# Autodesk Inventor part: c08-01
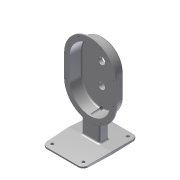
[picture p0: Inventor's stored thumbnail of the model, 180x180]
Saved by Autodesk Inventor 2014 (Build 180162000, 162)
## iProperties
Created: 2010-12
Part Number: c08-01
Document SubType Name: Modeling
Designer: Thom Tremblay
Density: 7.25 g/cm^3
Material: Iron, Cast
Mass: 1233.53 g
Surface Area: 883.619 cm^2
Volume: 170.142 cm^3
Appearance: Steel
Author: Thom Tremblay
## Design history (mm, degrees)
sketch "Sketch1"
  geometry: L1 (-50, -50)-(-50, 0); L2 (50, 0)-(50, -50); L3 (-60, 0)-(-60, -50); L4 (60, -50)-(60, 0); A1 r 50 centre (0, 0) between (50, 0) and (-50, 0); A2 r 50 centre (0, -50) between (-50, -50) and (50, -50); A3 r 60 centre (0, -50) between (-60, -50) and (60, -50); A4 r 60 centre (0, 0) between (60, 0) and (-60, 0); 1 further point
  constraints: 8 end point, 8 point on circle, 4 centre point, 4 tangent, 2 parallel, 1 coincident, 1 vertical, 3 other
  dimensions: "d0" = 50 distance of L2.start L2.end; "d1" = 50 radius of A1; "d2" = 10 radial gap between concentric circles of A4 A1
extrude "Extrusion1" new body sketch "Sketch1" distance "d3" = 30; taper "d4" = -2 deg
fillet "Fillet1" dims "d7" = 6
shell "Shell3" dims "d132" = 3
extrude "Extrusion2" join sketch "Sketch1" distance "d5" = 4; taper "d6" = -2 deg
fillet "Fillet12" dims "d133" = 2
fillet "Fillet13" dims "d134" = 1
workplane "Work Plane2"
sketch "Sketch7"
  geometry: C1 r 7.5 at (0, -95); 1 further point
  constraints: 1 centre point, 1 vertical alignment
  dimensions: "d64" = 15 diameter of C1; "d65" = 95 distance of point (0, 0) C1.centre
extrude "Extrusion8" join sketch "Sketch7" stored distance "d66" = 12.7; taper "d67" = 2 deg
fillet "Fillet2" dims "d9" = 3, "d10" = 1
hole "Hole3" diameter "d70" = 8; stored, may be unused: countersink angle "d74" = 82 deg, drill point angle "d76" = 118 deg; dims "d68" = 10, "d69" = 10, "d71" = 9, "d72" = 9.525, "d73" = 6.35, "d75" = 30, "d77" = 0.62479, "d78" = 7.985
workplane "Work Plane1"
sketch "Sketch2"
  geometry: L1 (-20.917, -1.5)-(20.917, -1.5); L2 (20.917, -1.5)-(20.219, -21.5); L3 (20.219, -21.5)-(16.219, -21.5); L4 (16.219, -21.5)-(15.695, -6.5); L5 (15.695, -6.5)-(-15.695, -6.5); L6 (-15.695, -6.5)-(-16.219, -21.5); L7 (-16.219, -21.5)-(-20.219, -21.5); L8 (-20.219, -21.5)-(-20.917, -1.5); L9 (-16.219, -21.5)-(16.219, -21.5); 3 further points
  constraints: 18 end point, 3 parallel, 2 equal length, 2 midpoint, 2 vertical alignment, 1 collinear, 1 horizontal
  dimensions: "d12" = 4 deg angle of L8 L6; "d13" = 88 deg angle of L8 L1; "d14" = 1.5 distance from line of point (0, 0) L1; "d15" = 20 vertical distance of L1.end L2.end; "d16" = 4 distance of L2.end L3.end; "d17" = 5 distance between parallel lines of L1 L5
extrude "Extrusion3" join sketch "Sketch2" stored distance "d18" = 27.94; taper "d19" = 0 deg
sketch "Sketch3"
  geometry: L1 (-70, -150)-(70, -150) reference; L2 (-50, -150)-(50, -150); L3 (50, -150)-(50, -144); L4 (50, -144)-(-50, -144); L5 (-50, -144)-(-50, -150); 2 further points
  constraints: 8 end point, 2 parallel, 1 horizontal, 1 midpoint, 1 perpendicular, 1 point on line, 1 vertical alignment
  dimensions: "d20" = 100 distance of L3.end L4.end; "d21" = 6 distance of L2.end L3.end
extrude "Extrusion4" join sketch "Sketch3" distance "d22" = 63.5; taper "d23" = 0 deg
feature "FaceDraft1" dims angle "d24" = 2 deg
sketch "Sketch4"
  geometry: L1 (-50, -150)-(50, -150) reference; L2 (50, -150)-(50, -143.773) reference; L3 (50, -143.773)-(-50, -143.773) reference; L4 (-50, -143.773)-(-50, -150) reference; 1 further point
extrude "Extrusion5" join sketch "Sketch4" distance "d25" = 63.5; taper "d26" = 0 deg
feature "FaceDraft2" dims angle "d27" = 2 deg
fillet "Fillet3" dims "d28" = 12
fillet "Fillet4"
fillet "Fillet5"
fillet "Fillet6" dims "d29" = 4
fillet "Fillet7" dims "d30" = 4
fillet "Fillet8" dims "d31" = 2
sketch "Sketch5"
  geometry: C1 r 12.5 at (0, 0); 1 further point
  constraints: 1 centre point, 1 coincident
  dimensions: "d32" = 25 diameter of C1
extrude "Extrusion6" join sketch "Sketch5" distance "d33" = 5; taper "d35" = -2 deg; dims "d34" = 8, "d36" = -2 deg
hole "Hole1" diameter "d40" = 14; stored, may be unused: countersink angle "d44" = 82 deg, drill point angle "d46" = 118 deg; dims "d38" = 10, "d39" = 10, "d41" = 19.05, "d42" = 9.525, "d43" = 6.35, "d45" = 25.4
sketch "Sketch10"
  geometry: C1 r 12.5 at (0, -50); A1 r 60 centre (0, -50) between (-60, -50) and (-18.704, -107.01) reference; 1 further point
  constraints: 1 centre point, 1 coincident
  dimensions: "d135" = 25 diameter of C1
extrude "Extrusion9" join sketch "Sketch10" distance "d136" = 12; taper "d137" = -2 deg
fillet "Fillet9" dims "d37" = 3
hole "Hole2" diameter "d55" = 14; stored, may be unused: countersink angle "d59" = 82 deg, drill point angle "d61" = 118 deg; dims "d53" = 10, "d54" = 10, "d56" = 19.05, "d57" = 9.525, "d58" = 6.35, "d60" = 8
hole "Hole4" diameter "d81" = 7; stored, may be unused: countersink angle "d85" = 82 deg, drill point angle "d87" = 118 deg; dims "d79" = 10, "d80" = 10, "d82" = 12.7, "d83" = 12.8778, "d84" = 6.35, "d86" = 30.48
hole "Hole5" diameter "d90" = 7; stored, may be unused: countersink angle "d94" = 82 deg, drill point angle "d96" = 118 deg; dims "d88" = 10, "d89" = 10, "d91" = 12.7, "d92" = 12.8778, "d93" = 6.35, "d95" = 30.48
hole "Hole6" diameter "d99" = 7; stored, may be unused: countersink angle "d103" = 82 deg, drill point angle "d105" = 118 deg; dims "d97" = 10, "d98" = 10, "d100" = 12.7, "d101" = 12.8778, "d102" = 6.35, "d104" = 30.48
hole "Hole7" diameter "d108" = 7; stored, may be unused: countersink angle "d112" = 82 deg, drill point angle "d114" = 118 deg; dims "d106" = 10, "d107" = 10, "d109" = 12.7, "d110" = 12.8778, "d111" = 6.35, "d113" = 30.48
fillet "Fillet11" dims "d122" = 1
node "Hole10"
chamfer "Chamfer1" distance "d138" = 1; stored, may be unused: second distance "d139" = 2, angle "d140" = 45 deg
body "Solid1"
node "Projected Loop1"
sketch "Sketch9"
  geometry: 8 further points
hole "Hole9" sketch "Sketch9" diameter "d123" = 3.242; stored, may be unused: countersink angle "d127" = 82 deg, drill point angle "d129" = 0 deg; dims "d124" = 19.05, "d125" = 9.525, "d126" = 6.35, "d128" = 25.4
other parameters: "d63" = -35
